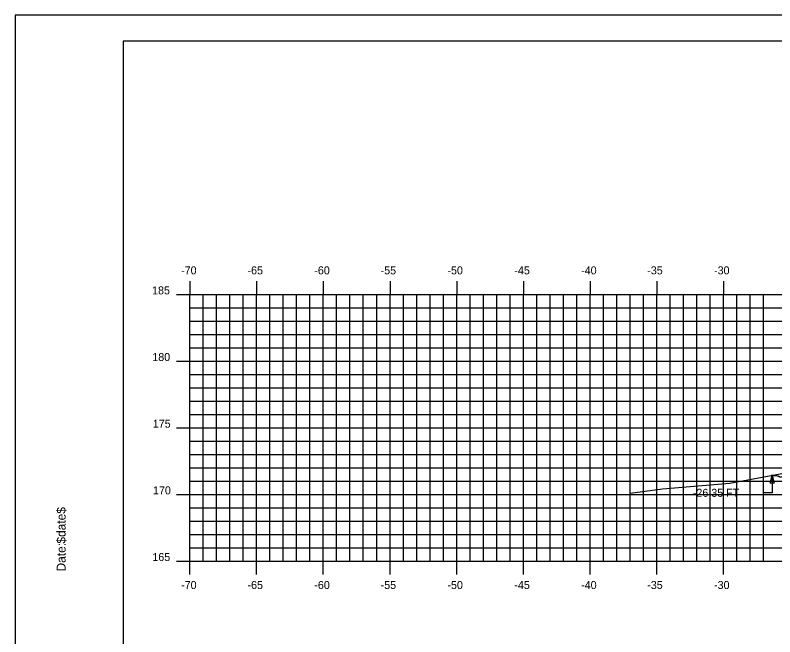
# Model space of a CAD drawing. Extents: x 1140315 to 1140485, y 608981 to 609091.
# Drawn here: x 1140315.4 to 1140372.3, y 609044.6 to 609091.3 of the extents above; entities that cross this region are included whole.
import ezdxf

# ---------------------------------------------------------------- set-up
doc = ezdxf.new("R2010")
doc.units = 0
for name, color, linetype in [('BORDER', 7, 'Continuous'), ('D_Roadway_SlopeLines', 7, 'Continuous'), ('D_Text_Standard', 7, 'Continuous'), ('H_V ANNOTATION', 7, 'Continuous'), ('MAJOR', 7, 'Continuous'), ('MINOR', 7, 'Continuous'), ('PLOT BOUNDARY', 7, 'Continuous'), ('S_Roadway_Centerline', 7, 'Continuous')]:
    doc.layers.add(name, color=color, linetype=linetype)

msp = doc.modelspace()

# ---------------------------------------------------------------- linework, layer by layer
msp.add_lwpolyline([(1140372.049, 609056.744), (1140372.227, 609056.762), (1140372.406, 609056.749), (1140372.585, 609056.706), (1140372.763, 609056.632), (1140375.763, 609057.632), (1140383.487, 609060.206), (1140383.488, 609060.206), (1140387.488, 609060.366), (1140398.488, 609060.586), (1140409.488, 609060.366), (1140413.488, 609060.206), (1140421.211, 609057.632), (1140424.211, 609056.632), (1140428.647, 609058.85), (1140429.897, 609059.403), (1140431.147, 609059.813), (1140432.397, 609060.079), (1140433.647, 609060.201)])
at = {"layer": 'BORDER'}
msp.add_lwpolyline([(1140323.488, 608984.335), (1140483.488, 608984.335), (1140483.488, 609089.335), (1140323.488, 609089.335)], close=True, dxfattribs=at)
at = {"layer": 'D_Roadway_SlopeLines'}
msp.add_lwpolyline([(1140372.763, 609056.632), (1140372.585, 609056.706), (1140372.406, 609056.749), (1140372.227, 609056.762), (1140372.049, 609056.744)], dxfattribs=at)
at = {"layer": 'D_Text_Standard'}
msp.add_lwpolyline([(1140372.138, 609056.753), (1140372.139, 609055.452), (1140371.459, 609055.452)], dxfattribs=at)
msp.add_lwpolyline([(1140372.138, 609056.753), (1140372.284, 609056.171), (1140371.993, 609056.171)], close=True, dxfattribs=at)
at = {"layer": 'MAJOR'}
for p, q in [((1140328.488, 609071.337), (1140328.488, 609070.335)), ((1140333.488, 609071.337), (1140333.488, 609070.335)), ((1140338.488, 609071.337), (1140338.488, 609070.335)), ((1140343.488, 609071.337), (1140343.488, 609070.335)), ((1140348.488, 609071.337), (1140348.488, 609070.335)), ((1140353.488, 609071.337), (1140353.488, 609070.335)), ((1140358.488, 609071.337), (1140358.488, 609070.335)), ((1140363.488, 609071.337), (1140363.488, 609070.335)), ((1140368.488, 609071.337), (1140368.488, 609070.335)), ((1140327.486, 609070.335), (1140328.488, 609070.335)), ((1140328.488, 609070.335), (1140468.488, 609070.335)), ((1140328.488, 609050.335), (1140328.488, 609070.335)), ((1140328.488, 609050.335), (1140328.488, 609070.335)), ((1140328.488, 609070.335), (1140468.488, 609070.335)), ((1140333.488, 609050.335), (1140333.488, 609070.335)), ((1140338.488, 609050.335), (1140338.488, 609070.335)), ((1140343.488, 609050.335), (1140343.488, 609070.335)), ((1140348.488, 609050.335), (1140348.488, 609070.335)), ((1140353.488, 609050.335), (1140353.488, 609070.335)), ((1140358.488, 609050.335), (1140358.488, 609070.335)), ((1140363.488, 609050.335), (1140363.488, 609070.335)), ((1140368.488, 609050.335), (1140368.488, 609070.335)), ((1140327.486, 609065.335), (1140328.488, 609065.335)), ((1140328.488, 609065.335), (1140468.488, 609065.335)), ((1140327.486, 609060.335), (1140328.488, 609060.335)), ((1140328.488, 609060.335), (1140468.488, 609060.335)), ((1140327.486, 609055.335), (1140328.488, 609055.335)), ((1140328.488, 609055.335), (1140468.488, 609055.335)), ((1140327.486, 609050.335), (1140328.488, 609050.335)), ((1140328.488, 609050.335), (1140468.488, 609050.335)), ((1140328.488, 609050.335), (1140468.488, 609050.335)), ((1140328.488, 609049.333), (1140328.488, 609050.335)), ((1140333.488, 609049.333), (1140333.488, 609050.335)), ((1140338.488, 609049.333), (1140338.488, 609050.335)), ((1140343.488, 609049.333), (1140343.488, 609050.335)), ((1140348.488, 609049.333), (1140348.488, 609050.335)), ((1140353.488, 609049.333), (1140353.488, 609050.335)), ((1140358.488, 609049.333), (1140358.488, 609050.335)), ((1140363.488, 609049.333), (1140363.488, 609050.335)), ((1140368.488, 609049.333), (1140368.488, 609050.335))]:
    msp.add_line(p, q, dxfattribs=at)
at = {"layer": 'MINOR'}
for p, q in [((1140329.488, 609050.335), (1140329.488, 609070.335)), ((1140330.488, 609050.335), (1140330.488, 609070.335)), ((1140331.488, 609050.335), (1140331.488, 609070.335)), ((1140332.488, 609050.335), (1140332.488, 609070.335)), ((1140334.488, 609050.335), (1140334.488, 609070.335)), ((1140335.488, 609050.335), (1140335.488, 609070.335)), ((1140336.488, 609050.335), (1140336.488, 609070.335)), ((1140337.488, 609050.335), (1140337.488, 609070.335)), ((1140339.488, 609050.335), (1140339.488, 609070.335)), ((1140340.488, 609050.335), (1140340.488, 609070.335)), ((1140341.488, 609050.335), (1140341.488, 609070.335)), ((1140342.488, 609050.335), (1140342.488, 609070.335)), ((1140344.488, 609050.335), (1140344.488, 609070.335)), ((1140345.488, 609050.335), (1140345.488, 609070.335)), ((1140346.488, 609050.335), (1140346.488, 609070.335)), ((1140347.488, 609050.335), (1140347.488, 609070.335)), ((1140349.488, 609050.335), (1140349.488, 609070.335)), ((1140350.488, 609050.335), (1140350.488, 609070.335)), ((1140351.488, 609050.335), (1140351.488, 609070.335)), ((1140352.488, 609050.335), (1140352.488, 609070.335)), ((1140354.488, 609050.335), (1140354.488, 609070.335)), ((1140355.488, 609050.335), (1140355.488, 609070.335)), ((1140356.488, 609050.335), (1140356.488, 609070.335)), ((1140357.488, 609050.335), (1140357.488, 609070.335)), ((1140359.488, 609050.335), (1140359.488, 609070.335)), ((1140360.488, 609050.335), (1140360.488, 609070.335)), ((1140361.488, 609050.335), (1140361.488, 609070.335)), ((1140362.488, 609050.335), (1140362.488, 609070.335)), ((1140364.488, 609050.335), (1140364.488, 609070.335)), ((1140365.488, 609050.335), (1140365.488, 609070.335)), ((1140366.488, 609050.335), (1140366.488, 609070.335)), ((1140367.488, 609050.335), (1140367.488, 609070.335)), ((1140369.488, 609050.335), (1140369.488, 609070.335)), ((1140370.488, 609050.335), (1140370.488, 609070.335)), ((1140371.488, 609050.335), (1140371.488, 609070.335)), ((1140328.488, 609069.335), (1140468.488, 609069.335)), ((1140328.488, 609069.335), (1140329.49, 609069.335)), ((1140328.488, 609068.335), (1140468.488, 609068.335)), ((1140328.488, 609068.335), (1140329.49, 609068.335)), ((1140328.488, 609067.335), (1140468.488, 609067.335)), ((1140328.488, 609067.335), (1140329.49, 609067.335)), ((1140328.488, 609066.335), (1140468.488, 609066.335)), ((1140328.488, 609066.335), (1140329.49, 609066.335)), ((1140328.488, 609064.335), (1140468.488, 609064.335)), ((1140328.488, 609064.335), (1140329.49, 609064.335)), ((1140328.488, 609063.335), (1140468.488, 609063.335)), ((1140328.488, 609063.335), (1140329.49, 609063.335)), ((1140328.488, 609062.335), (1140468.488, 609062.335)), ((1140328.488, 609062.335), (1140329.49, 609062.335)), ((1140328.488, 609061.335), (1140468.488, 609061.335)), ((1140328.488, 609061.335), (1140329.49, 609061.335)), ((1140328.488, 609059.335), (1140468.488, 609059.335)), ((1140328.488, 609059.335), (1140329.49, 609059.335)), ((1140328.488, 609058.335), (1140468.488, 609058.335)), ((1140328.488, 609058.335), (1140329.49, 609058.335)), ((1140328.488, 609057.335), (1140468.488, 609057.335)), ((1140328.488, 609057.335), (1140329.49, 609057.335)), ((1140328.488, 609056.335), (1140468.488, 609056.335)), ((1140328.488, 609056.335), (1140329.49, 609056.335)), ((1140328.488, 609054.335), (1140468.488, 609054.335)), ((1140328.488, 609054.335), (1140329.49, 609054.335)), ((1140328.488, 609053.335), (1140468.488, 609053.335)), ((1140328.488, 609053.335), (1140329.49, 609053.335)), ((1140328.488, 609052.335), (1140468.488, 609052.335)), ((1140328.488, 609052.335), (1140329.49, 609052.335)), ((1140328.488, 609051.335), (1140468.488, 609051.335)), ((1140328.488, 609051.335), (1140329.49, 609051.335))]:
    msp.add_line(p, q, dxfattribs=at)
at = {"layer": 'PLOT BOUNDARY'}
msp.add_lwpolyline([(1140315.395, 608981.276), (1140485.395, 608981.276), (1140485.395, 609091.276), (1140315.395, 609091.276)], close=True, dxfattribs=at)
at = {"layer": 'S_Roadway_Centerline'}
msp.add_lwpolyline([(1140361.498, 609055.42), (1140363.905, 609055.746), (1140368.956, 609056.168), (1140375.166, 609057.325)], dxfattribs=at)

# ---------------------------------------------------------------- texts
at = {"layer": 'BORDER'}
for s, p in [('$date$', (1140319.173, 609051.64)), ('Date:', (1140319.173, 609049.552))]:
    msp.add_text(s, height=0.6696, rotation=90, dxfattribs=at).set_placement(p)
at = {"layer": 'D_Text_Standard'}
msp.add_text('-26.35 FT', height=0.6, dxfattribs=at).set_placement((1140366.186, 609055.152))
at = {"layer": 'H_V ANNOTATION'}
for s, p in [('-70', (1140327.83, 609071.835)), ('-65', (1140332.806, 609071.835)), ('-60', (1140337.814, 609071.835)), ('-55', (1140342.784, 609071.835)), ('-50', (1140347.792, 609071.835)), ('-45', (1140352.806, 609071.835)), ('-40', (1140357.814, 609071.835)), ('-35', (1140362.768, 609071.835)), ('-30', (1140367.776, 609071.835)), ('185', (1140325.655, 609070.335)), ('180', (1140325.671, 609065.335)), ('175', (1140325.709, 609060.335)), ('170', (1140325.725, 609055.335)), ('165', (1140325.677, 609050.335)), ('-70', (1140327.83, 609048.235)), ('-65', (1140332.806, 609048.235)), ('-60', (1140337.814, 609048.235)), ('-55', (1140342.784, 609048.235)), ('-50', (1140347.792, 609048.235)), ('-45', (1140352.806, 609048.235)), ('-40', (1140357.814, 609048.235)), ('-35', (1140362.768, 609048.235)), ('-30', (1140367.776, 609048.235))]:
    msp.add_text(s, height=0.6, dxfattribs=at).set_placement(p)
at = {"layer": 'MAJOR'}
msp.add_text('-', height=0.006, dxfattribs=at).set_placement((1140328.483, 609050.335))

doc.saveas('drawing.dxf')
